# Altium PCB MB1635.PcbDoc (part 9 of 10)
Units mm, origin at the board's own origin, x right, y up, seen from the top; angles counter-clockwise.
Board outline 127 x 97 mm, 6 copper layers (Top Layer, Signal Layer 1, Signal Layer 2, Signal Layer 3, Signal Layer 4, Bottom Layer), stack 1.557 mm thick; 593 components, 478 nets, 2435 pads, 1743 vias.
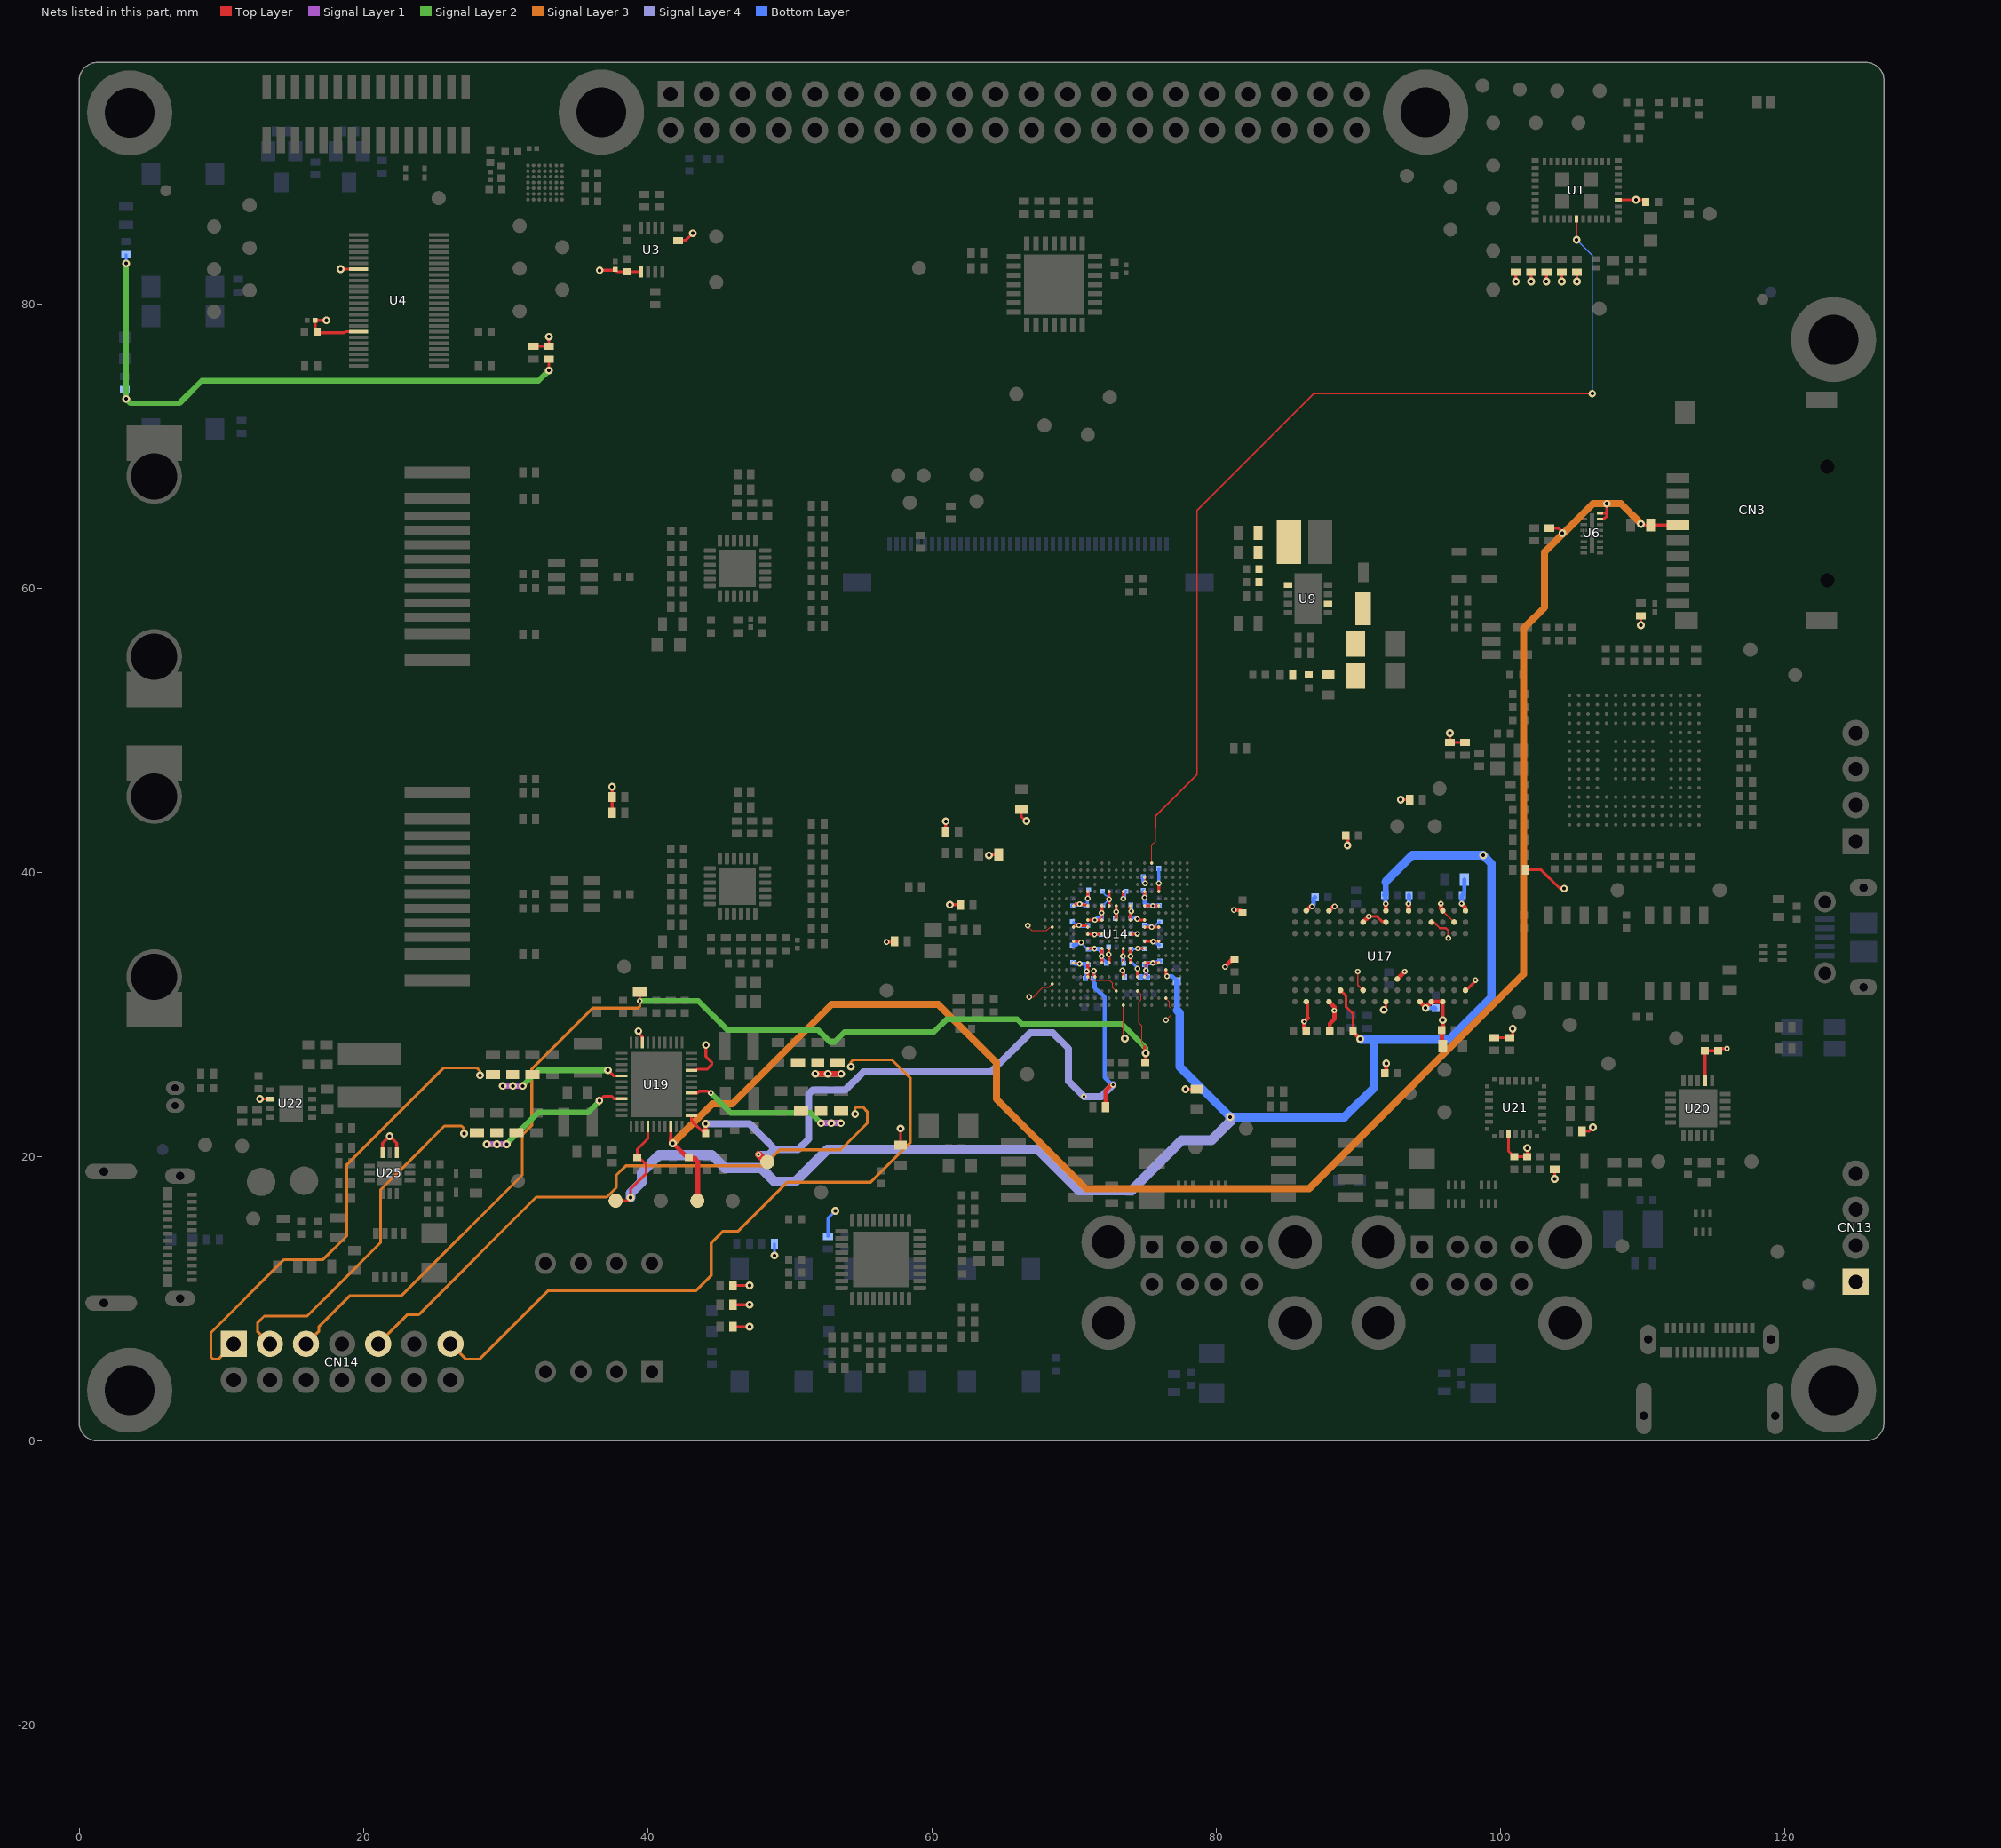
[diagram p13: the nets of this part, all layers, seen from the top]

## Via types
v1: diameter 0.55, hole 0.25, Top Layer to Bottom Layer, 1438 vias
v2: diameter 0.4, hole 0.2, Top Layer to Bottom Layer, 276 vias
v3: diameter 0.26, hole 0.1, Top Layer to Signal Layer 1, tented both sides, 29 vias

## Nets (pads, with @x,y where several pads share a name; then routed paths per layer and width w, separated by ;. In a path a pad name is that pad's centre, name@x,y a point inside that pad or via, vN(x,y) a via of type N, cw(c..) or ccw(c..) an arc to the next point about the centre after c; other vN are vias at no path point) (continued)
VDD: C15.2 C108.2 C109.2 C111.2 C138.2 C139.2 C171.2 C173.2 C176.2 C185.1 C190.2 C197.2 C201.2 C202.2 C205.2 C207.1 C208.2 C209.2 C215.1 CN13.1 CN14.13 R14.1 R15.1 R16.1 R17.1 R18.1 R21.2 R46.1 R62.2 R63.2 R71.2 R72.2 R75.2 R82.2 R94.2 R108.2 R120.2 R121.1 R123.2 R124.2 R141.2 R153.2 R154.2 R155.2 R172.2 R174.2 R180.2 R181.2 R187.2 R192.2 U1.36 U14.AA12 U14.C15 U14.E12 U14.E17 U14.G9 U14.G13 U14.J7 U14.J9 U14.J13 U14.K2 U14.M5 U14.N7 U14.N9 U14.N12 U14.R5 U14.R7 U14.R9 U14.R12 U14.U7 U14.V2 U14.W11 U14.Y18 U19.31 U19.42 U20.2 U21.3 U22.2 U25.10 U25.12 | length 171.5
  Top Layer w0.075: v2@66.75,36.2 67.046,35.904 68.079,35.904 68.302,36.127 68.452,36.127 U14.K2@68.475,36.15 ; v2(66.85,31.225) 67.15,31.225 67.825,31.9 68.225,31.9 U14.V2@68.475,32.15 ; U14.U7@70.975,32.65 71.224,32.401 72.512,32.401 72.727,32.187 72.727,32.186 72.728,32.184 72.728,31.897 U14.W11@72.975,31.65 ; v2(76.475,29.6) 76.85,29.975 76.85,30.425 76.725,30.55 76.725,30.899 U14.Y18@76.474,31.15
  Top Layer w0.09: v2@66.75,36.2 v2(66.75,36.25) ; U14.R5@69.975,33.65 70.002,33.623 70.405,33.623 70.449,33.58 70.444,33.575 v2(70.4,33.575) ; U14.AA12@73.475,30.65 73.475,28.45 v1@73.65,28.275 ; v1(73.575,28.3) v1@73.625,28.3 ; U14.C15@74.975,39.65 74.988,39.638 74.988,39.188 75,39.2 v2(75,39.225)
  Top Layer w0.175: U14.J7@70.975,36.65 v2(71.475,36.65) U14.J9@71.975,36.65 71.975,37.125 v2(71.95,37.15) ; U14.R12@73.475,33.65 73.45,33.675 v2(73.45,34.1) 73.45,34.625 U14.N12@73.475,34.65
  Top Layer w0.2: v1(12.725,24.05) U22.2@13.45,24.05 ; U25.12@21.345,20.264 21.345,20.939 v1(21.845,21.439) 22.345,20.939 U25.10@22.345,20.264 ; v1(33.05,75.325) R21.2@33.05,76.125 ; R75.2@37.5,44.2 R71.2@37.5,45.3 v1(37.5,46.025) ; v1(39.352,28.826) 39.419,28.759 39.419,28.634 39.625,28.428 U19.42@39.625,28.025 ; U19.31@43.075,26.075 43.403,26.075 43.408,26.07 43.489,26.15 43.529,26.15 43.53,26.151 44.201,26.151 44.517,26.467 44.517,26.633 44.102,27.048 v1(44.102,27.851) ; R153.2@46,8.025 v1(47.175,8.025) ; R154.2@46,9.575 v1(47.175,9.575) ; R155.2@46,10.925 v1(47.175,10.925) ; v2(56.825,35.1) 57.325,35.1 R108.2@57.375,35.15 ; R82.2@60.975,42.875 v1(60.975,43.6) ; v1(61.275,37.725) R192.2@62,37.725 ; U14.M5@69.975,35.15 69.979,35.146 70.375,35.146 70.446,35.075 v2(70.5,35.075) ; v2(70.9,33.05) 70.9,33.042 70.884,33.027 70.875,33.036 70.914,33.075 70.95,33.039 70.925,33.014 70.975,32.964 U14.U7@70.975,32.65 ; v2@70.925,33.136 70.975,33.186 U14.R7@70.975,33.65 ; U14.N7@70.975,34.65 71.425,34.65 v2(71.45,34.625) ; v2(71.95,37.15) 71.969,37.169 71.969,37.623 71.969,37.644 U14.G9@71.975,37.65 ; U14.R9@71.975,33.65 71.975,34.075 v2(71.95,34.1) 71.975,34.125 U14.N9@71.975,34.65 ; v2@73.475,38.148 U14.E12@73.475,38.65 ; U14.J13@73.975,36.65 73.975,37.178 74,37.203 v2@74,37.25 ; U14.G13@73.975,37.65 73.975,37.225 v2@74,37.25 ; v2(74.022,37.269) 74.02,37.269 v2@74,37.25 ; U14.E17@75.975,38.65 v2(75.975,39.225) ; v1(93,45.125) R72.2@93.625,45.125 ; v1(96.45,49.8) R62.2@96.45,49.15 R63.2@97.525,49.15 ; R120.2@99.575,28.375 R121.1@100.65,28.375 100.775,28.25 100.875,28.35 v1(100.875,29) ; U21.3@100.575,21.575 100.575,20.4 C138.2@100.975,20 C139.2@101.9,20 v1(101.9,20.6) ; v1(101.1,81.575) R14.1@101.1,82.25 ; R94.2@101.775,40.175 102.875,40.175 104.139,38.911 104.448,38.911 v1(104.5,38.858) ; v1(102.175,81.575) R15.1@102.175,82.25 ; v1(103.25,81.575) R16.1@103.25,82.25 ; v1(103.825,18.425) R141.2@103.825,19.1 ; v1(104.325,81.575) R17.1@104.325,82.25 ; v1(105.4,81.575) R18.1@105.4,82.25 ; R187.2@105.75,21.775 106.25,21.775 v1(106.525,22.05) ; U1.36@108.3,87.325 110.075,87.325 C15.2@110.225,87.175 ; v1(109.9,57.4) R46.1@109.9,58.05 ; U20.2@114.4,25.325 C108.2@114.4,27.45 C109.2@115.325,27.45 115.475,27.6 v2(115.95,27.6)
  Top Layer w0.4: v1(51.8,25.825) v1(52.675,25.825) v1(53.625,25.825)
  Signal Layer 1 w0.4: v1(51.8,25.825) v1(52.675,25.825) v1(53.625,25.825)
  Signal Layer 2 w0.4: v1(3.3,73.325) v1@3.3,73.343 ; v1(3.3,82.85) v1@3.3,73.343 ; v1@3.411,73.231 v1@3.305,73.338 ; v1(33.05,75.325) 32.325,74.6 8.625,74.6 7.05,73.025 3.618,73.025 v1@3.305,73.338 ; v1(51.8,25.825) v1(52.675,25.825) v1(53.625,25.825) ; v1@3.3,73.343 v1@3.305,73.338
  Signal Layer 3 w0.2: CN14.13@26.12,6.82 27.19,5.75 28.184,5.75 33.001,10.567 43.417,10.567 44.475,11.625 44.475,13.916 45.309,14.75 46.375,14.75 49.825,18.2 55.7,18.2 58.471,20.971 58.471,25.538 57.209,26.8 54.45,26.8 54.3,26.65 v1(54.3,26.325)
  Signal Layer 3 w0.4: v1(51.8,25.825) v1(52.675,25.825) v1(53.625,25.825)
  Signal Layer 4 w0.4: v1(51.8,25.825) v1(52.675,25.825) v1(53.625,25.825)
  Bottom Layer w0.09: C185.1@73.999,37.649 C185.1@74,37.65
  Bottom Layer w0.15: v2(70.5,35.075) 70.5,35.05 70.85,34.7 70.9,34.7 C201.2@71,34.6
  Bottom Layer w0.2: R174.2@3.205,73.988 3.3,73.893 v1(3.3,73.325) ; v1(3.3,82.85) 3.3,83.483 R172.2@3.305,83.488 ; v1(48.925,13.041) R181.2@48.925,13.85 ; R180.2@52.692,14.387 52.692,15.658 v1(53.209,16.175) ; v2@72.003,33.965 72.275,33.693 C209.2@72.275,33.6 ; C176.2@73.52,38.545 C176.2@73.65,38.675 ; v2(75.975,39.225) C171.2@75.975,40.275
  Bottom Layer w0.3: C207.1@69.975,33.675 70.075,33.575 v2(70.4,33.575) 70.916,33.575 70.92,33.58 C205.2@71,33.5 70.875,33.375 70.903,33.347 70.9,33.343 v2(70.9,33.05) 70.9,33.028 70.898,33.027 70.875,33.05 70.888,33.063 70.888,32.751 70.825,32.688 70.825,32.575 C215.1@70.8,32.55 ; C197.2@69.975,34.875 70,34.9 70.123,34.9 70.248,35.025 70.252,35.025 70.255,35.028 70.383,35.028 70.41,35.056 70.481,35.056 v2(70.5,35.075) ; C201.2@71,34.6 71.025,34.625 v2(71.45,34.625) 71.825,34.625 C202.2@71.9,34.55 71.95,34.5 v2(71.95,34.1) ; v2(71.475,36.65) 71.531,36.706 71.559,36.706 71.603,36.75 C190.2@71.925,36.75 71.95,36.775 v2(71.95,37.15) ; v2(73.45,34.1) 73.45,33.775 73.475,33.75 C208.2@73.525,33.7 ; v2@73.52,38.193 C176.2@73.52,38.545 ; C185.1@73.999,37.649 74.022,37.625 v2(74.022,37.269) ; C173.2@74.875,39.7 74.875,39.35 v2(75,39.225)
  other v1: 109.55,87.325
  other v2: 73.474,38.147
VDD_ADC: C132.2 C214.1 R133.2 TP66.1 U14.U8 U19.23 | length 53.7
  Top Layer w0.2: U19.23@43.075,22.875 43.075,22.55 C132.2@44.05,21.575 ; v2(71.4,33.075) 71.4,32.725 U14.U8@71.475,32.65
  Top Layer w0.3: C132.2@44.075,21.65 v1(44.075,22.3) ; R133.2@72.225,23.475 72.225,24.645 72.557,24.977 72.611,25.031 72.731,25.031 v2(72.75,25.05)
  Top Layer w0.5: v2(47.8,20.15) 48.325,19.625 TP66.1@48.425,19.625
  Signal Layer 4 w0.5: v1(44.075,22.3) 47.175,22.3 47.8,21.675 47.8,21.666 48.166,21.3 48.175,21.3 48.975,20.5 ; v2(47.8,20.15) 48.501,20.15 48.851,20.5 50.592,20.5 51.325,21.233 51.325,24.382 51.618,24.675 53.9,24.675 55.175,25.95 64.15,25.95 66.919,28.719 68.506,28.719 69.625,27.6 69.625,25.3 v2(70.7,24.225) 71.925,24.225 v2(72.75,25.05)
  Bottom Layer w0.3: v2(71.4,33.075) 71.375,33.05 71.375,32.575 C214.1@71.35,32.55 71.375,32.525 71.375,32.278 71.451,32.202 71.451,31.886 71.673,31.664 71.706,31.664 72.154,31.216 72.154,25.571 72.675,25.05 v2(72.75,25.05)
VDD_CORE: C124.2 C127.2 C133.2 C188.2 C189.2 C195.1 C196.2 C199.2 C200.2 C203.1 C213.2 CN14.9 R131.2 R132.2 U14.G11 U14.J11 U14.J15 U14.L7 U14.L9 U14.L13 U14.N10 U14.N13 U14.N15 U14.R10 U14.R13 U14.U12 U14.U14 U19.27 | length 73.4
  Top Layer w0.2: U19.27@43.075,24.475 43.504,24.475 43.63,24.601 44.224,24.601 44.312,24.513 44.412,24.513 v2(44.45,24.475) ; C133.2@57.8,20.8 v1(57.8,21.975) ; U14.L7@70.975,35.65 71.425,35.65 v2(71.45,35.625) 71.475,35.65 U14.L9@71.975,35.65 ; v2(72.45,34.225) 72.45,34.625 U14.N10@72.475,34.65 ; U14.R10@72.475,33.65 v2@72.475,34.225 ; U14.J11@72.975,36.65 72.975,37.149 v2(72.975,37.225) 72.975,37.198 U14.G11@72.975,37.65 ; U14.U12@73.475,32.65 73.475,32.875 v2@73.475,33.1 ; U14.R13@73.975,33.65 v2(73.975,34.1) ; U14.N13@73.975,34.65 v2@73.975,34.125 ; U14.L13@73.975,35.65 74.448,35.65 74.473,35.675 74.471,35.677 v2(74.454,35.677) ; v2(74.45,36.725) 74.525,36.65 U14.J15@74.974,36.65 ; U14.U14@74.475,32.65 v2@74.475,33.175 ; v2(74.5,34.65) U14.N15@74.975,34.65 ; v1(77.85,24.75) C124.2@78.65,24.75 ; v2(73.975,34.1) v2@73.975,34.125 ; v2(73.975,34.1) v2@73.975,34.125
  Signal Layer 1 w0.4: v1(52.2,22.35) v1(52.925,22.35) v1(53.6,22.35)
  Signal Layer 2 w0.4: v2(44.45,24.475) 45.849,23.076 51.474,23.076 v1(52.2,22.35) v1(52.925,22.35) v1(53.6,22.35)
  Signal Layer 3 w0.2: CN14.9@21.04,6.82 23.112,8.892 23.901,8.892 32.159,17.15 37.118,17.15 37.802,17.834 37.802,17.963 37.802,18.688 38.464,19.351 42.114,19.351 ; 42.115,19.35 48.159,19.35 49.284,20.475 53.584,20.475 55.45,22.341 55.45,23.175 55.15,23.475 54.692,23.475 54.575,23.358 54.575,23.025 v1(54.6,23)
  Signal Layer 3 w0.4: v1(52.2,22.35) v1(52.925,22.35) v1(53.6,22.35)
  Bottom Layer w0.2: v2(71.45,35.625) 71.675,35.625 71.7,35.65 C196.2@71.925,35.65 ; v2(72.45,34.225) 72.45,34.55 72.475,34.575 C203.1@72.45,34.6 ; C189.2@72.9,36.75 72.975,36.825 72.975,37.149 v2(72.975,37.225) ; v2@73.5,33.086 73.494,33.081 73.494,32.706 C213.2@73.55,32.65 ; C195.1@74,35.7 74.025,35.675 74.396,35.675 74.422,35.649 74.449,35.677 v2(74.454,35.677) 74.454,35.673 74.475,35.651 v2@74.461,35.637 ; C188.2@74,36.8 74.375,36.8 v2(74.45,36.725) ; v2@74.473,34.65 74.448,34.625 74.025,34.625 C200.2@74,34.6 73.975,34.575 v2(73.975,34.1) 73.994,34.081 73.994,33.938 74.025,33.907 74.025,33.712 74.425,33.312 74.425,33.302 74.475,33.252 v2(74.475,33.225) v2@74.475,33.2 ; v2@74.475,34.65 v2(74.5,34.65) 74.513,34.638 74.963,34.638 C199.2@74.975,34.625
  Bottom Layer w0.4: v1(52.2,22.35) v1(52.925,22.35) v1(53.6,22.35)
  other v2: 73.4,33.1
VDD_CPU: C66.2 C72.2 C115.2 C174.2 C177.1 C183.2 C186.2 C187.2 C191.1 C194.2 CN14.1 R126.2 R127.2 U14.E7 U14.E10 U14.G5 U14.G7 U14.G10 U14.K5 U14.K7 U19.5 | length 57.1
  Top Layer w0.2: v1(37.2,26.075) 37.225,26.075 37.625,25.675 U19.5@38.175,25.675 ; v1@64.15,41.25 C72.2@64.7,41.25 ; C66.2@66.3,44.45 66.3,43.925 66.625,43.6 v1@66.652,43.627 ; U14.K5@69.975,36.15 69.982,36.15 70.107,36.275 v2(70.35,36.275) 70.363,36.263 70.855,36.263 70.968,36.15 U14.K7@70.975,36.15 ; U14.G5@69.975,37.65 69.983,37.65 70.094,37.761 70.386,37.761 v2(70.4,37.775) ; v2@70.4,37.721 70.416,37.737 70.58,37.737 70.596,37.721 70.896,37.721 70.967,37.65 U14.G7@70.975,37.65 ; U14.E7@70.975,38.65 70.976,38.649 70.976,38.169 v2(70.977,38.168) ; U14.G10@72.475,37.675 v2(72.475,38.1) ; v2@72.475,38.125 U14.E10@72.475,38.65
  Signal Layer 1 w0.4: v1(29.8,24.975) v1(30.525,24.975) v1(31.2,24.975)
  Signal Layer 2 w0.4: v1(29.8,24.975) v1(30.525,24.975) v1(31.2,24.975) 32.3,26.075 v1(37.2,26.075)
  Signal Layer 3 w0.2: CN14.1@10.88,6.82 9.81,5.75 9.425,5.75 9.275,5.9 9.275,7.6 14.425,12.75 17.175,12.75 18.825,14.4 18.825,19.425 25.65,26.25 27.975,26.25 28.2,26.025 v1(28.2,25.725)
  Signal Layer 3 w0.4: v1(29.8,24.975) v1(30.525,24.975) v1(31.2,24.975)
  Bottom Layer w0.09: C186.2@72,37.625 v2(72.475,38.1)
  Bottom Layer w0.1: v2(70.35,36.275) 70.473,36.275 70.474,36.276 v2@70.441,36.276 ; C177.1@72,38.675 72.125,38.55 72.125,38.479 72.248,38.356 72.319,38.356 72.418,38.257 v2@72.418,38.157
  Bottom Layer w0.15: C191.1@69.975,36.525 69.975,36.425 70.075,36.425 70.177,36.323 70.394,36.323 v2@70.441,36.276
  Bottom Layer w0.2: C187.2@70.9,37.625 70.939,37.664 70.939,38.13 v2(70.977,38.168) 71.001,38.192 71.001,38.626 C174.2@71.025,38.65
  Bottom Layer w0.3: C183.2@69.9,37.625 69.925,37.65 70.038,37.65 70.113,37.725 v2@70.4,37.725 ; v2(70.4,37.775) 70.427,37.775 70.477,37.725 70.521,37.725 70.523,37.723 70.699,37.723 70.772,37.65 70.875,37.65 C187.2@70.9,37.625 ; v2@70.473,36.275 70.502,36.275 70.536,36.241 70.966,36.241 C194.2@70.975,36.25
  Bottom Layer w0.4: v1(29.8,24.975) v1(30.525,24.975) v1(31.2,24.975)
  other v1: 64.025,41.2 66.653,43.627
VDD_DDR: C70.2 C82.2 C94.2 C104.2 C105.2 C106.2 C112.2 C121.2 C128.2 C172.2 C175.2 C178.2 C179.2 C181.2 C182.2 C184.2 C192.2 C193.2 C198.2 C204.1 C206.2 C211.2 C212.2 C218.2 CN14.3 R137.2 R138.2 U14.E15 U14.G15 U14.G17 U14.K15 U14.K17 U14.M15 U14.M17 U14.R15 U14.R17 U14.U15 U17.A1 U17.A8 U17.B2 U17.C1 U17.C9 U17.D2 U17.D9 U17.E9 U17.F1 U17.G7 U17.H2 U17.H9 U17.K2 U17.K8 U17.N1 U17.N9 U17.R1 U17.R9 U19.9 | length 80.3
  Top Layer w0.09: v2(89.975,33.025) 89.975,32.075 U17.K8@90.35,31.7
  Top Layer w0.1: U17.H2@91.905,36.535 U17.H2@91.945,36.495 ; U17.C1@95.945,37.295 U17.B2@96.745,36.495
  Top Layer w0.125: U17.R9@86.35,30.9 U17.R9@86.463,30.787
  Top Layer w0.15: U17.D2@95.145,36.495 95.325,36.495 95.75,36.07 96.17,36.07 96.35,35.89 v2(96.35,35.375)
  Top Layer w0.175: 86.463,29.763 U17.R9@86.463,30.787
  Top Layer w0.2: v1(36.6,23.925) 36.901,24.226 37.473,24.226 37.648,24.051 38.151,24.051 U19.9@38.175,24.075 ; U14.U15@74.974,32.65 75.075,32.75 v2(75.075,33.1) 75.075,33.55 74.975,33.65 75.525,33.65 v2(75.55,33.625) 75.575,33.65 U14.R17@75.974,33.65 ; U14.M15@74.975,35.15 U14.M17@75.975,35.15 ; U14.K15@74.975,36.15 74.982,36.157 75.468,36.157 v2(75.475,36.15) ; U14.G15@74.975,37.65 v2(75.55,37.65) 75.556,37.656 75.948,37.656 75.969,37.656 U14.G17@75.975,37.65 ; v2(74.975,38.225) U14.E15@74.975,38.65 ; v2@75.404,36.15 v2(75.475,36.15) ; U14.K17@75.974,36.15 v2(75.475,36.15) ; v2(90.75,36.9) 91.325,36.9 91.69,36.535 U17.H2@91.905,36.535 ; v1@91.775,30.3 v1(91.8,30.325) 91.95,30.475 U17.H9@91.95,30.9 ; U17.A8@97.55,31.7 97.6,31.7 98.212,32.312 98.212,32.386 v2(98.25,32.425)
  Top Layer w0.3: v2(80.625,33.35) 81.175,33.9 C94.2@81.3,33.9 ; v2(81.25,37.35) 81.65,37.35 C82.2@81.85,37.15 ; C105.2@86.35,28.85 86.2,29 v2(86.2,29.5) 86.463,29.763 ; U17.R1@86.35,37.3 86.631,37.581 86.731,37.581 v2(86.75,37.6) ; U17.N9@87.95,30.9 88.325,30.525 v2(88.325,30.275) 88.325,29.675 88,29.35 C106.2@88,28.85 ; U17.N1@87.95,37.3 88.231,37.581 88.331,37.581 v2(88.35,37.6) ; C70.2@89.125,42.575 89.25,42.45 v1(89.25,41.9) ; U17.K2@90.345,36.495 v2@90.719,36.869 ; C121.2@91.875,25.875 91.975,25.975 91.975,26.525 v1@91.95,26.55 ; U17.G7@92.745,32.495 v2(93.275,33.025) ; v2(93.545,37.795) 93.545,37.305 U17.F1@93.55,37.3 ; U17.E9@94.345,30.895 v1@94.745,30.495 ; v1@94.745,30.495 U17.D9@95.15,30.9 U17.C9@95.95,30.9 95.945,30.895 95.945,29.575 95.955,29.565 95.955,28.925 C104.2@95.895,28.865 ; v2(95.825,37.8) 95.825,37.452 95.945,37.332 U17.C1@95.945,37.295 ; C104.2@95.895,28.895 C104.2@95.895,28.865 ; C112.2@95.945,27.845 95.895,27.895 C104.2@95.895,28.865 ; v2(97.275,37.8) 97.531,37.544 97.531,37.319 U17.A1@97.55,37.3
  Signal Layer 1 w0.4: v1(28.675,20.875) v1(29.4,20.875) v1(30.075,20.875)
  Signal Layer 2 w0.4: v1(28.675,20.875) v1(29.4,20.875) v1(30.075,20.875) 32.3,23.1 35.825,23.1 36.6,23.875 v1(36.6,23.925)
  Signal Layer 3 w0.2: CN14.3@13.42,6.82 12.55,7.69 12.55,8.3 13.025,8.775 16.041,8.775 18.35,11.084 21.2,13.934 21.2,15.334 21.2,17.65 23.15,19.6 25.7,22.15 26.9,22.15 27.075,21.975 v1(27.075,21.625)
  Signal Layer 3 w0.4: v1(28.675,20.875) v1(29.4,20.875) v1(30.075,20.875)
  Bottom Layer w0.15: C193.2@74.975,36.275 C193.2@75,36.25 ; v2@75.394,36.169 75.456,36.169 v2(75.475,36.15) 75.523,36.198 75.648,36.198 75.85,36.4 75.925,36.4 C192.2@76.025,36.5
  Bottom Layer w0.175: 74.925,32.65 74.975,32.7 ; C204.1@74.975,33.525 C204.1@74.975,33.625
  Bottom Layer w0.2: v2@75.575,35.1 75.588,35.087 75.734,35.087 75.895,34.925 75.975,34.925 C198.2@76.025,34.875
  Bottom Layer w0.3: C212.2@74.65,32.65 74.925,32.65 C211.2@75.2,32.65 ; C175.2@74.875,38.675 74.975,38.575 v2(74.975,38.225) 74.975,37.8 C184.2@75.1,37.675 75.125,37.65 v2(75.55,37.65) 75.57,37.655 cw(c75.628,37.36) 75.629,37.66 75.921,37.66 cw(c75.922,37.36) 75.984,37.654 C182.2@75.999,37.651 ; 74.975,32.7 75.075,32.8 v2(75.075,33.1) 75.075,33.425 C204.1@74.975,33.525 ; C204.1@75,33.625 v2(75.55,33.625) 75.569,33.644 75.84,33.644 75.921,33.725 76.025,33.725 C206.2@76.05,33.75 ; C193.2@75,36.25 75.314,36.25 v2@75.394,36.169 ; v2(86.75,37.6) 86.75,37.627 86.87,37.747 86.87,38.145 C181.2@86.975,38.25 ; v2(93.545,37.795) 93.575,37.825 C179.2@93.575,38.4 ; v1(94.75,30.45) 95.24,30.45 95.265,30.425 95.335,30.495 C218.2@95.425,30.405 ; v2(97.275,37.8) 97.294,37.819 97.294,38.369 97.475,38.55 C172.2@97.475,39.5
  Bottom Layer w0.4: v1(28.675,20.875) v1(29.4,20.875) v1(30.075,20.875)
  other v1: 91.975,26.55 95.95,29.605
  other v2: 75.575,35.125
VDD_LS: C16.2 C17.2 C24.2 C25.2 R6.2 R20.1 R21.1 U3.1 U4.7 U4.18 | length 12.5
  Top Layer w0.2: v1(17.4,78.85) C24.2@16.6,78.85 16.6,78.2 16.825,77.975 18.672,77.975 18.747,78.05 U4.18@19.725,78.05 ; v1(18.4,82.45) U4.7@19.65,82.45 ; U4.18@19.1,78.05 U4.18@19.65,78.05 ; R20.1@31.975,77.025 R21.1@33.05,77.025 v1(33.05,77.7) ; v1(36.625,82.375) 37.65,82.375 C17.2@37.715,82.44 37.89,82.265 C16.2@38.515,82.265 U3.1@39.54,82.265 ; R6.2@42.14,84.465 42.148,84.473 42.673,84.473 v1(43.175,84.975)
VDD_SD: C27.2 C144.2 CN3.4 R34.2 TP71.1 U6.15 U6.16 U19.20 | length 128
  Top Layer w0.2: 41.625,21.3 U19.20@41.625,22.125 ; R34.2@103.45,64.225 104.1,64.225 v1@104.45,63.875 ; U6.15@107.025,64.875 107.294,64.875 107.5,65.081 107.5,65.3 ; U6.16@107.025,65.275 107.475,65.275 107.5,65.3 ; v1(107.5,65.95) 107.5,65.3 ; v1@110,64.45 C27.2@110.575,64.45 CN3.4@112.5,64.45
  Top Layer w0.3: 41.625,21.3 41.625,21.095 41.785,20.935 42.69,20.03 42.795,20.03 C144.2@42.9,19.925
  Top Layer w0.4: C144.2@42.925,19.925 42.98,19.87 43.266,19.87 43.5,19.636 TP71.1@43.5,16.9
  Signal Layer 3 w0.5: v1(41.775,20.925) 44.55,23.7 45.937,23.7 52.938,30.701 60.458,30.701 64.554,26.605 64.554,24.046 70.849,17.751 86.551,17.751 101.65,32.85 101.65,57.175 103.125,58.65 103.125,62.545 104.365,63.786 104.365,63.865 v1(104.375,63.875) 104.45,63.875 106.525,65.95 v1(107.5,65.95) 108.5,65.95 109.9,64.55 v1(109.9,64.525)
VDD_USB: C119.2 CN14.5 R113.2 U14.W14 | length 82.4
  Top Layer w0.075: U14.W14@74.475,31.65 74.721,31.404 74.721,31.048 74.559,30.886 74.559,29.406 74.775,29.19 74.775,27.975 74.95,27.8
  Top Layer w0.2: v2(39.45,30.95) R113.2@39.45,31.575 R113.2@39.45,31.6 ; 74.975,27.725 74.975,27.475 74.95,27.45 75.05,27.35 v1(75.05,27.275) 75.05,26.925 74.95,26.825 C119.2@75.15,26.625
  Signal Layer 2 w0.4: v2(39.45,30.95) 43.575,30.95 45.625,28.9 52,28.9 52.834,28.066 53.166,28.066 53.856,28.756 60.131,28.756 61.05,29.675 66,29.675 66.356,29.319 73.386,29.319 74.169,28.536 74.95,27.755 74.95,27.725 75.05,27.625 v1(75.05,27.275)
  Signal Layer 3 w0.2: CN14.5@16.113,6.973 16.875,7.735 16.875,8.041 19.034,10.2 22.675,10.2 31.175,18.7 31.175,21.516 31.85,22.191 31.85,26.166 36.135,30.45 39.333,30.45 39.45,30.568 v2(39.45,30.95)
VH: C45.2 C51.2 C52.2 C56.2 D2.2 R60.1 U9.6
VL: C29.1 C31.2 C34.2 L3.1 R35.2 U9.1
VREF_DDR: C107.1 C141.2 C180.1 C210.1 TP69.1 U14.T18 U17.H1 U17.M8 U19.16 | length 117.8
  Top Layer w0.15: C107.1@89.65,28.75 C107.1@89.65,28.85
  Top Layer w0.175: v2@76.475,32.836 76.55,32.761 v2(76.55,32.7)
  Top Layer w0.2: TP69.1@37.75,16.9 38.57,16.9 v1@38.8,17.13 ; v1(38.8,17.125) v1@38.8,17.13 ; U19.16@40.025,22.125 40.025,21.275 39.275,20.525 C141.2@39.275,19.925 39.43,19.77 39.571,19.77 39.9,19.441 39.9,18.832 38.8,17.732 38.8,17.134 v1@38.8,17.13 ; v2@76.475,32.836 U14.T18@76.475,33.15 ; U17.M8@88.75,31.7 89.15,31.3 89.15,30.525 89.65,30.025 C107.1@89.65,28.85
  Top Layer w0.3: C107.1@89.65,28.75 v1@90.175,28.225 ; U17.H1@91.945,37.26 v2@91.945,37.775
  Signal Layer 4 w0.7: v1(38.8,17.125) 38.8,17.424 39.578,18.202 39.578,18.874 40.814,20.11 44.523,20.11 45.433,19.2 47.975,19.2 48.925,18.25 50.4,18.25 52.65,20.5 52.783,20.5 67.477,20.5 70.352,17.625 74.059,17.625 77.583,21.149 79.674,21.149 81,22.475 v1(81,22.775)
  Bottom Layer w0.3: v2(76.55,32.7) 76.9,32.7 C210.1@77.25,32.35 ; C180.1@91.875,38.4 91.926,38.349 91.926,37.814 v2(91.945,37.795)
  Bottom Layer w0.4: 77.25,30.3 C210.1@77.25,32.35 ; C180.1@91.875,38.4 91.928,38.453 91.928,39.329
  Bottom Layer w0.6: 77.25,30.3 77.435,30.115 77.435,26.34 v1(81,22.775) 89.025,22.775 91.1,24.85 91.1,28.225 ; v1(90.15,28.275) 90.2,28.225 91.1,28.225 ; 91.928,39.329 93.809,41.21 v1(98.795,41.21) 99.375,40.63 99.375,31.2 96.4,28.225 91.1,28.225
WL_HOST_WAKE: U1.27 U14.A16 | length 70.1
  Top Layer w0.075: U14.A16@75.475,40.65 75.475,41.275 75.475,41.931 75.75,42.206 75.75,43.125
  Top Layer w0.1: 75.75,43.125 75.75,43.983 78.65,46.883 78.65,65.475 86.875,73.7 v1(106.475,73.7) ; v1(105.375,84.525) U1.27@105.375,85.975
  Bottom Layer w0.1: v1(105.375,84.525) 106.475,83.425 v1(106.475,73.7)
pads on no net: CART-1.1 CN1.16 CN1.17 CN1.18 CN1.19 CN1.20 CN1.21 CN1.22 CN1.23 CN1.24 CN1.25 CN1.26 CN1.27 CN1.28 CN1.29 CN1.30 CN3.13 CN3.NPTH1 CN3.NPTH2 CN4.9 CN7.A2 CN7.A3 CN7.A8 CN7.A10 CN7.A11 CN7.B2 CN7.B3 CN7.B8 CN7.B10 CN7.B11 CN10.4 CN12.A2 CN12.A3 CN12.A6 CN12.A7 CN12.A8 CN12.A10 CN12.A11 CN12.B2 CN12.B3 CN12.B6 CN12.B7 CN12.B8 CN12.B10 CN12.B11 CN14.11 CN14.12 CN15.9 CN16.5 CN16.6 CN16.13 CN16.14 CN16.21 CN16.22 Designator1.1 Designator2.1 Designator3.1 Designator4.1 Designator5.1 Designator6.1 L1.2 SW1.5 U1.13 U1.15 U1.16 U2.A1 U2.A3 U2.A5 U2.B1 U2.B2 U2.B5 U2.B6 U2.B7 U2.C2 U5.7 U5.10 U6.1 U6.2 U7.4 U9.5 U12.A1 U12.A2 U12.A3 U12.A4 U12.A5 U12.A8 U12.A9 U12.A11 U12.A12 U12.A13 U12.B1 U12.B2 U12.B3 U12.B4 U12.B5 U12.B6 U12.B7 U12.B8 U12.B9 U12.B10 U12.B11 U12.B12 U12.B13 U12.B15 U12.C2 U12.C3 U12.C4 U12.C11 U12.C12 U12.C13 U12.C14 U12.C15 U12.D1 U12.D2 U12.D3 U12.D4 U12.D10 U12.D11 U12.D13 U12.D14 U12.E1 U12.E2 U12.E3 U12.E4 U12.E12 U12.E13 U12.E14 U12.E15 U12.F1 U12.F4 U12.F14 U12.F15 U12.G4 U12.G14 U12.G15 U12.H1 U12.H2 U12.H3 U12.H4 U12.H14 U12.H15 U12.J2 U12.J3 U12.J4 U12.K1 U12.K2 U12.K3 U12.K12 U12.K14 U12.K15 U12.L1 U12.L12 U12.L13 U12.L14 U12.L15 U12.M2 U12.M3 U12.M4 U12.M5 U12.M7 U12.M12 U12.M13 U12.M14 U12.M15 U12.N2 U12.N4 U12.N5 U12.N6 U12.N7 U12.N11 U12.N13 U12.N14 U12.N15 U12.P2 U12.P4 U12.P5 U12.P6 U12.P7 U12.P8 U12.P9 U12.P10 U12.P11 U12.P12 U12.P13 U12.P14 U12.P15 U12.R2 U12.R3 U12.R6 U12.R7 U12.R8 U12.R9 U12.R10 U12.R11 U12.R12 U17.J1 U17.J9 U17.L1 U17.L9 U18.4 U19.14 U19.33 U19.34 U21.1 U21.2 U21.6 U21.7 U21.10 U21.11 U21.12 U21.23 U21.24 U22.9 U25.11 U26.4 U27.4 U28.4 U29.4 U32.4
copper on no net: | length 0.8
  Top Layer w0.2: v1(98.933,45.558) 98.987,45.558 99.14,45.404 99.521,45.404 99.65,45.275
  other v1: 14.375,22.725 15.475,22.725 14.925,23.725 14.375,24.725 15.475,24.725

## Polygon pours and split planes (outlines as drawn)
5V_VIN on Signal Layer 4 "5V_VIN" (solid, pour order 139): 125.9,99.475 128.975,96.4 128.975,3.825 121.925,-3.225 -0.85,-3.225 -2.525,-1.55 -2.525,99.475
VDD on Signal Layer 4 "VDD_L05_P024" (solid, pour order 24): 70.575,28.625 71.673,29.723 71.673,32.798 72.236,33.36 73.435,33.36 73.65,33.575 73.65,34.225 73.121,34.225 73.025,34.321 72.275,34.321 71.948,34.648 71.756,34.84 71.394,34.934 71.363,34.965 71.363,36.363 71.938,36.363 72.423,36.848 73.286,36.848 73.564,37.127 74.427,37.127 74.723,37.423 74.723,38.473 72.898,38.473 72.898,37.873 70.948,37.873 70.625,37.55 70.625,35.825 70.398,35.598 36.648,35.598 35.681,36.565 35.681,36.669 30.131,36.669 30.1,36.7 29.775,36.375 29.775,27.703 31.752,25.727 45.146,25.727 45.35,25.93 45.35,26.725 46.025,27.4 46.875,27.4 47.5,26.775 47.5,25.923 50.125,25.923 51.073,24.975 54.65,24.975 55.6,25.923 64.225,25.923 66.775,28.473 66.775,28.625
VDD_CPU on Signal Layer 4 "VDD_CPU_L05_P022" (solid, pour order 22): 70.75,47.425 30.975,47.425 24.775,41.225 24.775,27.275 27.866,24.184 31.159,24.184 31.65,24.675 31.65,25.675 29.65,27.675 29.65,38.9 29.925,39.175 32.95,39.175 36.35,35.775 36.35,35.725 69.99,35.725 70.55,36.075 70.55,37.525 70.95,37.925 72.663,37.925 72.813,38.075 72.812,38.45 74.469,38.45 74.675,38.656 74.675,43.5
NetC71_2 on Signal Layer 4 "NO_FT" (solid, pour order 14): 30.125,39.05 36.6,39.05 40.55,43 42.4,43 43.725,41.675 43.725,40.831 42.75,39.856 42.75,34.9 42.475,34.625 41.575,34.625 41.375,34.825 37.525,34.825 35.65,36.7 30.1,36.7 29.85,36.95 29.85,38.775
3V3_SW on Signal Layer 4 "3V3_SW" (solid, pour order 124): 52.975,17.4 60.575,17.4 62.525,15.45 62.525,7 60.25,4.725 51.725,4.725 49.775,6.675 49.775,14.2
1V8_PERIPH on Signal Layer 4 "1V8_PERIPH" (solid, pour order 128): 40.2,88.725 40.2,86.796 39.118,85.715 37.81,85.715 36.925,86.575 28.976,86.575 28.25,85.849 28.25,78.125 27.7,77.575 26.9,77.575 26.9,77.75 23.1,81.55 23.1,85.375 23,85.375 21.8,86.575 16.588,86.575 15.808,85.795 15.808,75.467 9.6,69.259 9.6,14.125 11.694,12.031 42.931,12.031 44.3,13.4 44.3,15.75 44.65,16.1 46.325,16.1 46.7,15.725 46.7,-1.175 2.445,-1.175 -1.325,2.595 -1.325,95.65 0.475,97.45 39.825,97.45 40.175,97.025 40.2,97
VDD_CORE on Signal Layer 4 "VDD_CORE_L05_P018" (solid, pour order 18): 73.724,34.158 73.724,33.574 73.475,33.325 72.053,33.325 71.6,32.872 71.6,29.723 71.6,29.65 70.575,28.625 68.675,28.625 66.775,28.625 66.775,28.55 63.925,25.7 55.325,25.7 54.325,24.7 52.05,24.7 51.45,24.1 51.45,21.1 52.325,20.225 70.8,20.225 71.643,20.225 72.599,19.268 73.308,19.268 75.197,21.157 77.727,21.157 79.366,22.795 79.366,23.634 77.1,25.9 77.1,29.325 75.814,30.611 75.832,31.642 74.725,32.75 74.725,33.408 75.193,33.785 75.193,36.482 74.775,36.9 74.775,36.925 74.175,36.925 74.075,36.825 73.425,36.825 73.292,36.959 73.259,36.959 73.259,37.32 73.121,37.458 72.825,37.458 72.592,37.225 72.592,36.892 72.417,36.892 71.875,36.35 71.875,35.875 71.841,35.841 71.234,35.841 71.234,35.409 71.595,35.409 71.756,35.247 71.756,34.84 72.26,34.336 72.274,34.323 72.274,34.1 72.649,34.1 72.666,34.117 72.666,34.337 73.664,34.337 73.724,34.276
3V3_STLK on Signal Layer 4 "3V3_STLK" (solid, pour order 122): 97.8,45.9 97.8,43.712 100.965,40.547 100.965,38.735 101.762,37.937 117.837,37.937 120.75,35.025 120.75,28.075 121.975,26.85 127.225,26.85 127.3,26.925 127.3,58.775 104.525,58.775 97.8,52.05
NetC28_2 on Signal Layer 4 "NO_FT" (solid, pour order 78): 30.125,61.58 36.6,61.58 39.825,64.805 43.125,64.805 43.725,64.205 43.725,63.361 43.196,62.832 43.196,57.876 42.475,57.155 40.02,57.155 39.225,57.95 36.93,57.95 30.375,57.95 29.85,58.475 29.85,61.305
NetC221_2 on Signal Layer 4 "NO_FT" (solid, pour order 102): 108.95,16.925 107.625,18.25 107.625,22.85 106.45,24.025 106.45,24.8 107.425,25.775 112.625,25.775 115.425,28.575 115.425,31.1 115.975,31.65 116.875,31.65 117.35,31.175 117.35,22.775 111.5,16.925
NetC161_2 on Signal Layer 4 "NO_FT" (solid, pour order 16): 8.675,18.8 7.1,18.8 4.55,16.25 4.55,12.7 5.775,11.475 7.575,11.475 10.125,11.475 11.138,11.475 11.694,12.031 11.694,12.631 10.5,13.825 10.5,14.575 10.975,15.05 13.663,15.05 14.15,15.538 14.15,17.75 13.1,18.8
VDD_DDR on Signal Layer 4 "VDD_DDR_L05_P020" (solid, pour order 20): 74.73,53 82.68,45.05 85.072,45.05 88.025,45.05 89.675,43.4 89.675,38.125 98.475,38.125 98.475,29.35 92.358,29.35 92.358,22.841 79.347,22.841 76,26.975 74.806,28.45 74.806,43.369 70.85,47.325 30.8,47.325 24.65,41.175 24.65,27.3 30.381,21.569 30.381,20.631 30.075,20.325 25.225,20.325 18.425,27.125 18.425,46.325 25.1,53
NetC221_2 on Signal Layer 4 "NO_FT" (solid, pour order 86): 117.9,11.45 117.9,6.5 116.3,4.9 113.275,4.9 111.425,6.75 111.463,8.913 110.625,9.75 110.625,14.175 111.3,14.85 115.6,14.85 117.9,12.55
NetC87_2 on Signal Layer 4 "NO_FT" (solid, pour order 96): 105.2,30.975 105.75,31.525 114.325,31.525 114.95,30.9 114.95,30.025 114.375,29.45 105.425,29.45 105.2,29.675
GND on Top Layer "GND" (solid, remove dead copper, pour order 160): 1.7,97.825 127.425,97.825 127.875,97.375 127.875,1.15 123.975,-2.75 0.6,-2.75 -3.5,1.35 -3.5,97.536
GND on Top Layer "NO_FT" (solid, pour order 169): 98.025,94.95 96.15,96.825 92.8,96.825 91.475,95.5 91.475,91.8 93.275,90 96.9,90 98.025,91.125
GND on Top Layer "NO_FT" (solid, pour order 168): 40.025,94.95 38.15,96.825 34.8,96.825 33.475,95.5 33.475,91.8 35.275,90 38.9,90 40.025,91.125
I_SENSE_VDD on Top Layer "NO_FT" (solid, pour order 62): 53.575,28.85 54.6,27.825 54.6,27.6 54.4,27.4 48.825,27.4 48.025,26.6 46.9,26.6 46.775,26.725 46.775,28.75 46.875,28.85
NetL11_1 on Top Layer "NO_FT" (solid, remove dead copper, pour order 36): 36.65,22.175 36.65,21.45 36.525,21.325 35.75,21.325 35.65,21.425 35.65,23.4 35.8,23.55 37.3,23.55 37.65,23.375 37.725,23.375 37.725,23.175 37.65,23.175
5V_VIN on Top Layer "NO_FT" (solid, pour order 34): 36.05,20.9 36.05,19.813 35.15,18.7 34.95,18.7 34.95,17.925 36.675,17.925 36.825,18.075 36.825,20.825 38.575,22.575 38.575,22.975 37.65,22.975 36.775,22.1 36.775,21.575
5V_VIN on Top Layer "NO_FT" (solid, remove dead copper, pour order 32): 36.975,24.575 36.7,24.575 36.025,25.25 34.975,25.25 34.875,25.15 34.875,23.9 35.05,23.725 36,23.725 36.65,24.375 36.975,24.375
NetL7_1 on Top Layer "NO_FT" (solid, remove dead copper, pour order 26): 38,24.975 37.525,24.975 36.975,25.525 36.975,26.275 36.7,26.55 34.75,26.55 34.575,26.375 34.575,25.475 34.725,25.325 36.125,25.325 36.675,24.775 38,24.775
NetC160_1 on Top Layer "NO_FT" (solid, pour order 68): 17.475,14.579 17.475,13.854 17.05,13.429 17.05,10.904 17.425,10.529 23.3,10.529 23.775,11.004 23.775,13.304 23.3,13.779 20.275,13.779 19.925,13.429 19.925,12.754 19.8,12.629 18.975,12.629 18.85,12.754 18.85,14.629 18.75,14.729 17.625,14.729
VL on Top Layer "NO_FT" (solid, pour order 110): 82.35,64.675 82.35,62 82.6,61.75 82.6,60.025 82.7,59.925 85.4,59.925 85.45,59.975 85.45,61.325 85.5,61.375 85.9,61.375 86.2,61.675 86.2,64.925 86,65.125 82.8,65.125 82.375,64.7
NetC87_2 on Top Layer "NO_FT" (solid, pour order 92): 112.525,35.6 112.675,35.75 116.25,35.75 116.85,35.15 116.85,32.75 116.575,32.475 115.675,32.475 115.3,32.1 115.3,30.65 114.775,30.125 112.75,30.125 112.525,30.35
NetC161_2 on Top Layer "NO_FT" (solid, pour order 66): 13.475,16.275 19.2,16.275 19.425,16.05 19.425,15.45 19.025,15.05 13.525,15.05 13.125,15.45 13.125,15.925 13.375,16.175
VDD on Top Layer "NO_FT" (solid, pour order 64): 49.875,25.8 50.175,25.5 54.175,25.5 54.625,25.95 54.625,26.925 54.325,27.225 49.975,27.225 49.875,27.125
VDD_CORE on Top Layer "NO_FT" (solid, pour order 56): 50.1,22.375 50.4,22.075 54.4,22.075 54.85,22.525 54.85,23.5 54.55,23.8 50.2,23.8 50.1,23.7
I_SENSE_VDD_CORE on Top Layer "NO_FT" (solid, pour order 54): 46.65,24.8 46.975,25.125 54.75,25.125 54.975,24.9 54.975,24.3 54.65,23.975 48.675,23.975 48.175,23.475 48.175,22.875 48.05,22.75 46.925,22.75 46.65,23.025
VDD_DDR on Top Layer "NO_FT" (solid, pour order 42): 31.475,20.85 31.175,20.55 27.175,20.55 26.725,21 26.725,21.975 27.025,22.275 31.375,22.275 31.475,22.175
I_SENSE_VDD_DDR on Top Layer "NO_FT" (solid, pour order 38): 34.8,23.475 34.525,23.75 26.875,23.75 26.5,23.375 26.5,22.6 26.65,22.45 33.05,22.45 33.275,22.225 33.275,21.325 33.475,21.125 34.525,21.125 34.8,21.4
VDD_CPU on Top Layer "NO_FT" (solid, pour order 30): 32.6,24.95 32.3,24.65 28.3,24.65 27.85,25.1 27.85,26.075 28.15,26.375 32.5,26.375 32.6,26.275
"I_SENSE_VDD CPU" on Top Layer "NO_FT" (solid, pour order 28): 36.625,28.5 36.875,28.25 36.875,27.475 36.75,27.35 34.625,27.35 34,26.725 28.075,26.725 27.8,27 27.8,27.5 28,27.7 32.775,27.7 33.575,28.5
GND on Top Layer "NO_FT" (solid, pour order 143): 13.725,25.022 13.522,25.225 12.3,25.225 12.15,25.375 12.15,26.025 12.355,26.23 13.48,26.23 14.567,27.317 17.605,27.317 17.975,26.947 17.975,26.275 17.997,26.275 18.472,25.8 18.125,25.453 18.125,24.578 17.882,24.335 16.201,24.326 16.125,24.25 16.125,21.95 15.575,21.4 12.45,21.4 12.05,21.8 12.05,22.775 12.245,22.97 12.994,22.97 13.141,23.117 13.641,23.117 13.725,23.201
VH on Top Layer "NO_FT" (solid, pour order 114): 88.675,59.275 89.225,59.825 91.45,59.825 91.55,59.725 91.55,57.5 91.05,57 91.05,53 90.625,52.575 89.15,52.575 88.525,53.2 87.475,53.2 87.2,53.475 85.1,53.475 85,53.575 85,54.275 85.1,54.375 87.925,54.375 88.7,55.15 88.7,58.325 88.425,58.6 87.575,58.6 87.5,58.675 87.5,59.2 87.575,59.275
3V3_AO on Top Layer "NO_FT" (solid, pour order 74): 15.5,28.975 15.85,29.325 17.575,29.325 18.1,28.8 22.475,28.8 22.95,28.325 22.95,26.497 22.453,26 18.25,26 17.975,26.275 17.975,27.1 17.65,27.425 15.725,27.425 15.5,27.65
NetL8_1 on Top Layer "NO_FT" (solid, pour order 72): 17.39,23.7 15.991,23.704 15.85,23.844 15.85,24.233 16.023,24.406 17.943,24.396 18.125,24.578 18.125,25.453 18.472,25.8 22.578,25.8 22.85,25.528 22.85,23.55 22.425,23.125 18.319,23.125 17.745,23.7
5V_VIN on Top Layer "NO_FT" (solid, remove dead copper, pour order 58): 46.55,27.025 46.625,26.95 46.625,25.3 46.55,25.225 45.025,25.225 44.55,24.75 43.525,24.75 43.5,24.775 43.5,24.975 43.525,25 43.979,25 45.987,27.025
5V_VIN on Top Layer "NO_FT" (solid, remove dead copper, pour order 46): 46.075,20 46.95,20 47.3,20.35 47.3,20.975 46.625,21.65 46.625,21.975 46.625,22.725 45.05,22.725 44.375,23.4 43.525,23.4 43.5,23.375 43.5,23.175 43.525,23.15 43.649,23.15 44.762,21.975 45.299,21.975 45.35,21.926 45.35,21.663 45.6,21.4 45.95,21.05 45.95,20.125
NetC28_2 on Top Layer "NO_FT" (solid, pour order 80): 24.7,61.53 22.655,61.53 22.475,61.35 22.475,59.75 22.695,59.53 31.6,59.53 31.675,59.605 31.675,61.38 31.525,61.53
NetC71_2 on Top Layer "NO_FT" (solid, pour order 76): 22.65,39 22.325,38.675 22.325,37.3 22.625,37 31.6,37 31.675,37.075 31.675,38.85 31.525,39
NetL9_1 on Top Layer "NO_FT" (solid, remove dead copper, pour order 52): 43.525,23.55 43.5,23.575 43.5,23.775 43.525,23.8 43.8,23.8 44.947,24.95 45.875,24.95 45.925,24.9 45.925,22.9 45.875,22.85 45.125,22.85 44.425,23.55
NetL6_1 on Top Layer "NO_FT" (solid, remove dead copper, pour order 60): 43.525,25.15 43.5,25.175 43.5,25.375 43.525,25.4 43.675,25.4 43.875,25.6 43.875,26 44.5,26.625 44.5,28.8 44.55,28.85 45.875,28.85 45.925,28.8 45.925,27.35 45.925,26.8 45.875,26.75 45.5,26.75 43.9,25.15
NetD2_1 on Top Layer "NO_FT" (solid, pour order 112): 86.375,65.05 86.375,61.475 86.525,61.325 87.375,61.325 87.5,61.2 87.5,60 87.575,59.925 90.575,59.925 90.975,60.325 90.975,62.75 88.525,65.2 86.525,65.2
GND on Top Layer "NO_FT" (solid, pour order 167): 6.825,94.9 4.95,96.775 1.6,96.775 0.275,95.45 0.275,91.75 2.075,89.95 5.7,89.95 6.825,91.075
GND on Top Layer "NO_FT" (solid, pour order 170): 126.775,78.95 124.9,80.825 121.55,80.825 120.225,79.5 120.225,75.8 121.85,74.175 125.825,74.175 126.775,75.125
GND on Top Layer "NO_FT" (solid, pour order 171): 126.775,5 124.9,6.875 121.55,6.875 120.225,5.55 120.225,1.85 122.025,0.05 125.65,0.05 126.775,1.175
GND on Top Layer "NO_FT" (solid, pour order 172): 6.875,5.05 5,6.925 1.65,6.925 0.325,5.6 0.325,1.9 2.125,0.1 5.75,0.1 6.875,1.225
5V_VIN on Top Layer "5V_VIN" (solid, pour order 159): 21.195,15.214 21.67,15.689 25.995,15.689 26.37,16.064 27.145,16.064 27.445,15.764 27.445,14.939 27.095,14.589 26.02,13.514 23.844,13.514 23.395,13.964 21.345,13.964 21.195,14.114
3V3_STLK on Top Layer "NO_FT" (solid, pour order 108): 105.875,58.2 106.025,58.05 106.025,57 105.85,56.825 100.85,56.825 100.75,56.925 100.75,57.75 101.2,58.2
NetC36_1 on Top Layer "NO_FT" (solid, pour order 106): 97.325,56.825 97.425,56.725 100.1,56.725 100.225,56.6 100.225,55.925 100.15,55.85 98.6,55.85 98.4,55.65 98.4,54.875 98.6,54.675 100.1,54.675 100.7,55.275 100.7,57.55 100.475,57.775 98.875,57.775 98.3,58.35 98.3,59.475 98.075,59.7 97.45,59.7 97.325,59.575
NetD1_2 on Top Layer "NO_FT" (solid, pour order 104): 98.05,60.475 97.275,59.7 97.275,58.75 97.15,58.625 96.425,58.625 96.275,58.775 96.275,63.025 96.4,63.15 97.825,63.15 98.05,62.925
5V_VIN on Top Layer "NO_FT" (solid, pour order 100): 105,35.725 105.15,35.575 105.15,30.75 104.675,30.275 102.875,30.275 101.975,31.175 101.975,35.1 102.6,35.725
SRC_GDCS on Top Layer "NO_FT" (solid, pour order 98): 104,38.25 104.5,38.75 107.925,38.75 108.425,38.25 108.425,36.525 108.05,36.15 106.675,36.15 106.475,36.35 106.475,37.625 106.225,37.875 105.525,37.875 105.325,37.675 105.325,36.3 105.15,36.125 104.25,36.125 104,36.375
NetC87_2 on Top Layer "NO_FT" (solid, pour order 94): 105.3,35.575 105.55,35.825 107.875,35.825 108.3,35.4 108.3,30.725 107.7,30.125 105.625,30.125 105.3,30.45
SNK_GDCS on Top Layer "NO_FT" (solid, pour order 90): 111.125,38.25 111.625,38.75 115.05,38.75 115.55,38.25 115.55,36.525 115.175,36.15 113.8,36.15 113.6,36.35 113.6,37.625 113.35,37.875 112.65,37.875 112.45,37.675 112.45,36.3 112.275,36.125 111.375,36.125 111.125,36.375
PWR_ON_DB on Top Layer "NO_FT" (solid, pour order 88): 112.35,29.525 112.125,29.3 110.175,29.3 110.05,29.425 110.05,30.35 109.4,31 109.4,35.575 109.575,35.75 112.175,35.75 112.35,35.575
NetR140_2 on Top Layer "NO_FT" (solid, pour order 44): 38.65,22.525 38.925,22.525 38.925,21.7 37.975,20.75 37.975,20.175 37.925,20.125 37.025,20.125 36.95,20.2 36.95,20.825
GND on Bottom Layer "GND" (solid, remove dead copper, pour order 173): 1.7,97.825 127.425,97.825 127.875,97.375 127.875,1.15 123.85,-2.875 2.45,-2.875 -3.625,3.2 -3.625,97.529
GND on Bottom Layer "NO_FT" (solid, pour order 165): 91.475,94.95 93.35,96.825 96.7,96.825 98.025,95.5 98.025,91.8 96.225,90 92.6,90 91.475,91.125
GND on Bottom Layer "NO_FT" (solid, pour order 161): 5.05,96.675 6.925,94.8 6.925,91.45 5.6,90.125 1.9,90.125 0.1,91.925 0.1,95.55 1.225,96.675
GND on Bottom Layer "NO_FT" (solid, pour order 162): 4.95,6.825 6.825,4.95 6.825,1.6 5.5,0.275 1.8,0.275 0,2.075 0,5.7 1.125,6.825
GND on Bottom Layer "NO_FT" (solid, pour order 163): 120.175,5 122.05,6.875 125.4,6.875 126.725,5.55 126.725,1.85 124.925,0.05 121.3,0.05 120.175,1.175
GND on Bottom Layer "NO_FT" (solid, pour order 164): 120.125,79 122,80.875 125.35,80.875 126.675,79.55 126.675,75.85 124.875,74.05 121.25,74.05 120.125,75.175
GND on Bottom Layer "NO_FT" (solid, pour order 166): 33.475,94.95 35.35,96.825 38.7,96.825 40.025,95.5 40.025,91.8 38.225,90 34.6,90 33.475,91.125
NetC221_2 on Bottom Layer "NO_FT" (solid, pour order 150): 110.4,17.75 111.375,17.75 112.025,17.1 112.025,12.1 111.575,11.65 110.375,11.65 110.1,11.925 110.1,13.025 109.525,13.6 109.525,15.85 110.25,16.575 110.25,17.6
5V_VIN on Bottom Layer "NO_FT" (solid, pour order 82): 26.075,15.835 26.075,14.765 26.264,14.576 27.064,14.576 27.414,14.926 27.414,15.859 27.233,16.04 26.28,16.04
VDD on Signal Layer 3 "VDD" (solid, pour order 132): 125.9,99.475 128.975,96.4 128.975,3.825 121.925,-3.225 0.375,-3.225 -3.75,0.9 -3.75,99.475
3V3_AO on Signal Layer 3 "3V3_AO" (solid, pour order 120): 68.142,87.383 70.667,87.383 71.725,86.325 71.713,82.488 72.9,81.3 74.225,81.3 75.625,82.7 107.975,82.7 108.475,83.2 108.475,84.4 107.75,85.125 107.75,97.9 -1.55,97.9 -1.55,30.4 1.95,26.9 17.625,26.9 24.3,33.575 38.8,33.575 41.275,31.1 46.987,31.1 49.075,33.225 54.75,38.9 54.75,40.2 54.75,41.35 50.775,45.325 19.925,45.3 15.525,49.7 15.525,72.225 18.575,75.275 18.575,75.467 31.792,75.467 37.625,81.3 37.625,84.35 37.575,84.4 40.558,87.383
VDD_LS on Signal Layer 3 "VDD_LS" (solid, pour order 116): 43.1,87.275 43.458,86.917 43.458,84.557 43.05,84.15 38.338,84.15 37.5,83.312 37.5,81.175 31.9,75.575 18.575,75.575 17.209,76.941 17.209,79.058 17.65,79.5 17.65,82.125 18.725,83.2 22.7,83.2 23.234,82.666 23.234,81.216 26.825,77.625 27.65,77.625 28.3,78.275 28.3,85.75 29.025,86.475 38.2,86.475 39,87.275
3V3_SW on Signal Layer 3 "3V3_SW" (solid, pour order 126): 40.825,67.55 40.475,67.2 40.475,54.6 40.825,54.25 49.225,54.25 53.5,58.525 53.5,66.275 52.225,67.55
GND on Signal Layer 1 "GND_L02_P156" (solid, remove dead copper, pour order 156): 1.325,98.675 127.05,98.675 127.5,98.225 127.5,2 122.975,-2.525 1.375,-2.525 -5.2,4.05 -5.2,98.312
GND on Signal Layer 2 "GND_L03_P152" (solid, remove dead copper, pour order 152): 1.225,98.5 126.95,98.5 127.4,98.05 127.4,1.825 123.9,-1.675 -4,-1.675 -4,98.21

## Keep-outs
Keep-Out Layer:
  region: 0,0 0,97 127,97 127,0 2,0 2,2.5 124.5,2.5 124.5,94.5 2.5,94.5 2.5,0

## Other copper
Top Layer:
  region: 126,83.575 ccw(c126.05,83.575) 126.05,83.525 126.45,83.525 ccw(c126.45,83.575) 126.5,83.575 126.5,94.475 ccw(c126.45,94.475) 126.45,94.525 118.875,94.525 118.875,94.025 126,94.025
  pour cut-out: 117,95.45 cw(c116.925,95.45) 116.925,95.375 109.8,95.375 ccw(c109.8,94.2) 108.625,94.2 108.625,91.2 cw(c108.55,91.2) 108.55,91.125 108.075,91.125 ccw(c108.075,90.975) 107.925,90.975 107.925,88.475 ccw(c108,88.475) 108,88.4 108.904,88.4 ccw(c108.904,90.472) 110.975,90.472 110.975,92.894 cw(c111.106,92.894) 111.106,93.025 116.925,93.025 cw(c116.925,92.95) 117,92.95 117,83 128.05,83 128.05,97.4 117,97.4
  pour cut-out: 31.075,90.45 34.675,90.45 34.675,86.55 31.075,86.55
  pour cut-out: 104.75,50.025 103.15,51.625 101.775,51.625 101.775,50.7 103.325,50.7 104.55,49.475 105.075,49.475
  pour cut-out: 116.4,43.375 115.35,43.375 114.55,44.175 114.55,45.225 114.15,45.625 114.15,47.725 112.675,49.2 112.675,50.38 112.948,50.653 112.975,50.625 116.975,50.625 117.45,50.15 117.45,43.46 117.205,43.215
  pour cut-out: 108.5,41.15 108.5,42.05 109.05,42.6 109.05,43.5 111.575,43.5 111.725,43.35 111.725,42.475 112.275,41.925 112.275,41.15
  pour cut-out: 71.425,62.45 85.75,76.775 104.05,76.775 104.775,76.05 106.875,76.05 107.231,75.694 107.037,75.5 100.575,75.5 99.875,74.8 100.45,74.225 105.7,74.225 106.075,73.85 105.875,73.65 104,73.65 103.6,73.25 102.725,73.25 101.625,72.15 87.375,72.15 86.625,72.9 86.625,75.1 86.225,75.5 85.775,75.5 72.05,61.775 71.175,61.775
  pour cut-out: 72.725,55.9 76.25,55.9 76.3,55.95 76.3,50.2 75.4,49.3 73.9,49.3 72.725,50.475
  pour cut-out: 69.475,49.175 69.475,61.85 69.575,61.95 72.425,61.95 72.525,61.85 72.525,49.075 71.825,48.375 69.925,48.375
  pour cut-out: 65.525,61.45 66.725,61.45 66.775,61.4 66.775,55.975 66.4,55.6 66.325,55.675 65.625,55.675
  pour cut-out: 62.575,47.7 63.325,47.7 63.675,48.05 63.675,53.05 62.82,53.905 61.493,53.905 61.493,53.818 61.125,53.45 61.125,52.575 62.575,51.125
  pour cut-out: 61.45,50.869 61.45,43.95 60.575,43.075 60.575,40.85 61.375,40.05 61.425,40.1 62.475,40.1 62.962,40.587 62.962,44.088 61.95,45.1 61.95,50.825
  pour cut-out: 59.475,44.2 59.475,49.025 59.525,49.075 59.55,49.05 60.15,49.05 60.4,48.8 60.4,44.325 60.1,44.025
  pour cut-out: 52.75,54.35 54.7,54.35 54.975,54.075 54.975,46.325 54.7,46.05 53.675,46.05 52.75,46.975
  pour cut-out: 47.27,57.7 47.737,58.167 47.737,60.112 47.875,60.25 49,60.25 51.025,58.225 52.05,58.225 52.275,58.45 52.275,65.65 52.425,65.8 48.8,65.8 48.1,65.1 44.025,65.1 42.17,63.245 42.17,57.955 42.425,57.7
  pour cut-out: 51.547,35.15 52.075,35.678 52.075,43.15 51.688,43.537 43.587,43.537 42.175,42.125 42.175,35.425 42.45,35.15
  pour cut-out: 50.47,11.47 50.47,14.195 50.8,14.525 51.875,14.525 52.65,13.75 53.65,13.75 53.65,12.25
  pour cut-out: 59.1,13.025 59.1,14.2 61,16.1 62.2,16.1 62.25,16.05 62.25,15.425 62.1,15.275 61.5,15.275 60.675,14.45 60.675,13.525 60.05,12.9 58.975,12.9
  pour cut-out: 55.6,9.75 55.6,8.175 55.675,8.25 57.375,8.25 57.375,7.5 57.475,7.4 61.85,7.4 62.1,7.65 62.1,9 59.85,11.25 59.15,11.25 57.975,10.075 56.15,10.075
  pour cut-out: 49.875,8.275 49.875,6.611 50.375,6.111 50.375,6.075 52.725,8.425 54.575,8.425 55.4,9.25 55.4,10 51.6,10
  pour cut-out: 46.4,6 46.4,5.65 48.75,3.3 49.25,3.3 49.25,3.675 46.925,6
  pour cut-out: 67.125,41.5 67.125,41.575 77.25,41.575 77.75,42.075 96.1,42.075 96.575,41.6 99.95,38.225 99.9,38.175 99.9,32.425 97.375,29.9 94.4,29.9 94.075,29.575 90.925,26.425 90.775,26.425 80.7,26.425 77.025,30.1 67.125,30.075
  text "1" at 123.175,17.55 h1.5 r90
Signal Layer 1:
  pour cut-out: 117,97.4 128.05,97.4 128.05,83 117,83
  text "2" at 123.175,18.8 h1.5 r90
Signal Layer 2:
  pour cut-out: 117,97.4 128.05,97.4 128.05,83 117,83
  pour cut-out: 102.95,29.275 102.975,29.3 116.5,29.3 116.5,28.825 116.425,28.75 116.4,28.775 102.925,28.775
  pour cut-out: 100.109,26.559 117.739,26.559 118.01,26.287 117.748,26.025 100.075,26.025
  pour cut-out: 98.175,27.95 98.391,27.734 98.391,27.388 100.037,27.388 100.475,26.95 100.45,26.925 100.45,25.875 99.745,25.875 98.82,24.95 97.225,24.95 96.3,25.875 93.275,25.875 92.925,26.225 92.925,26.925 97.15,26.925
  pour cut-out: 91.925,26.825 74.425,26.825 74.316,26.716 74.316,26.159 74.6,25.875 92.075,25.875 92.1,25.85
  pour cut-out: 81.769,16.657 86.061,20.95 87.55,20.95 87.025,21.475 84.925,21.475 81.7,18.25 68.925,18.25 66.1,15.425 66.1,13.575 66.625,13.05 70.2,16.625 81.725,16.625
  pour cut-out: 50.95,21.625 71.3,21.625 72.025,20.9 71.3,20.175 51.35,20.175 49.675,18.5 48.65,18.5 48.45,18.7
  pour cut-out: 37.225,27.975 36.625,28.575 24.425,28.575 24.125,28.275 24.125,27.75 28.3,27.75 29.525,26.525 36.2,26.525 37.3,27.625
  pour cut-out: 22.875,58.775 36.375,58.775 36.775,59.175 41.3,59.175 41.7,58.775 41.862,58.937 45.363,58.937 45.625,58.675 45.25,58.3 23.35,58.3
  pour cut-out: 56,74 56.7,73.3 56.7,71.625 58.05,70.275 63.575,70.275 64.6,69.25 68.825,69.25 69.475,68.6 68.95,68.075 56.225,68.075 55.75,68.55 16.141,68.55 15.808,68.883 15.808,71.133 16.5,71.825 19.1,71.825 19.675,72.4 19.675,73.575 20.1,74
  pour cut-out: 33.975,84.375 55.1,84.375 55.75,83.725 65.65,83.725 66.05,83.325 65.6,82.875 33.75,82.875 33.075,83.55
  pour cut-out: 44.6,78.925 89.355,78.925 89.997,78.283 89.997,78.117 89.792,78.117 89.575,77.9 89.075,78.4 66.655,78.4 65.905,77.65 65.905,77.42 66.275,77.05 66.85,77.05 66.875,77.025 66.875,76.55 66.775,76.45 62.675,76.45 62.1,75.875 62.35,75.625 80.814,75.625 81.148,75.291 80.982,75.125 71.625,75.125 70.15,73.65 70.075,73.725 63.25,73.725 62.8,74.175 50.1,74.175 48.925,75.35 48.925,77 48,77.925 44.625,77.925
  pour cut-out: 51.65,80.45 51.65,80.87 51.755,80.975 50.65,80.975 50.525,81.1 50.525,81.475 32.391,81.475 31.95,81.034 31.95,80.55
  pour cut-out: 48.7,80.15 58,80.15 58.15,80 58.15,79.525 58.125,79.5 48.825,79.5
  text "3" at 123.175,20.05 h1.5 r90
Signal Layer 3:
  pour cut-out: 117,97.4 128.05,97.4 128.05,83 117,83
  text "4" at 123.175,21.3 h1.5 r90
Signal Layer 4:
  pour cut-out: 117,97.4 128.05,97.4 128.05,83 117,83
  text "5" at 123.175,22.55 h1.5 r90
Bottom Layer:
  pour cut-out: 29.126,79.486 29.95,78.662 29.95,28.248 29.586,27.883 29.192,27.883 29.125,27.95 29.126,27.951
  pour cut-out: 28.676,48.277 29.125,47.829 29.125,30.896 28.791,30.563 28.687,30.563 28.35,30.9 28.35,47.951
  pour cut-out: 117,97.4 128.05,97.4 128.05,83 117,83
  pour cut-out: 90.531,41.1 98.95,41.1 99.8,40.25 99.8,30.875 96.525,27.6 92.3,27.6 91.725,27.025 91.725,24.625 89.425,22.325 80.873,22.325 76.965,26.234 76.965,32.131 75,34.096 75,34.65 75,36.015 75,37.725 77.3,40.025 77.3,41.725 78.125,42.55 78.125,44.325 78.925,45.125 88.625,45.125 89.425,44.325 89.425,42.206
  pour cut-out: 77.25,32.05 77.25,26.775 78.025,26 78.403,26 78.715,26.312 78.715,30.685 77.975,31.425 77.975,32.25 77.35,32.25 77.25,32.35
  pour cut-out: 106.475,73.7 106.475,75.025 107.075,75.625 107.075,85.55 106.475,86.15 104.25,86.15 104.05,86.35 104.05,92.675 103.975,92.75 103.375,92.75 103.375,86 101.625,84.25 101.625,75.225 103.675,73.175 105.975,73.175
  pour cut-out: 54.325,46 54.325,50.45 52.3,52.475 52.3,56.75 51.525,57.525 51.525,74.175 51.95,74.6 51.95,76.35 51.025,77.275 49.25,77.275 48.775,76.8 48.775,66.2 48.325,65.75 48.325,60.175 48.375,60.125 49.075,60.125 50.388,58.812 50.388,55.588 49.6,54.8 49.6,49.55 49.725,49.55 53.275,46
  pour cut-out: 29.775,79.975 30.875,79.975 31.15,80.25 30.95,80.45 30.95,86.95 30.3,87.6 26.95,87.6 26.7,87.35 26.725,87.325 26.725,82.05 27.125,81.65 27.125,79 27.975,78.15 29.175,78.15 29.95,78.925 29.95,79.3
  pour cut-out: 21,69.725 21.4,70.125 21.4,71.925 22.725,73.25 22.725,77.225 23.15,77.65 23.15,79.5 22.925,79.725 22.925,81.625 22.225,81.625 22.225,78.075 21.025,76.875 21.025,74.65
  pour cut-out: 67.6,43 68.325,43 69.425,41.9 69.425,39.2 69.739,38.886 69.816,38.886 69.816,38.637 69.529,38.35 68.825,38.35 68.575,38.6 68.575,41.425 67.6,42.4
  text "6" at 123.175,23.8 h1.5 r90
Multi-Layer:
  pour cut-out: 121.8,17.425 123.55,17.425 123.55,25.05 121.8,25.05

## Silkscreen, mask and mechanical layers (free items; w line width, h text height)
Top Overlay:
  lines w0.1: 41.6,18.25 42.925,18.25 ; 41.625,16.3 42.6,16.3 ; 42.15,16.3 42.15,18.225 ; 44.05,18.4 45.375,18.4 ; 44.05,36.05 50.1,36.05 50.375,36.325 50.375,44.3 ; 44.2,16.075 45.525,16.075 ; 44.875,16.075 44.875,18.4 ; 48.85,44.3 55.925,44.3 56.175,44.3 56.175,47.325 48.85,47.325 48.85,44.3
  lines w0.12: 34.4,90.55 34.8,90.55 34.8,90.15
  text "H" at 49.725,83.025 h20
  text "S" at 81.225,81.075 h12
  text "F" at 43.4,72.4 h15
  text "ETH2" at 17.125,70.125 h2
  text "J" at 65.075,60.3 h20
  text "MB1635E" at 65.175,57.375 h3
  text "I" at 55,50.025 h15
  text "C" at 63.3,48.85 h15
  text "ETH1" at 17.225,47.575 h2
  text "E" at 79.425,42.6 h15
  text "G" at 69.25,42.075 h12
  text "PWR_IN" at 0.65,21.85 h1.5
